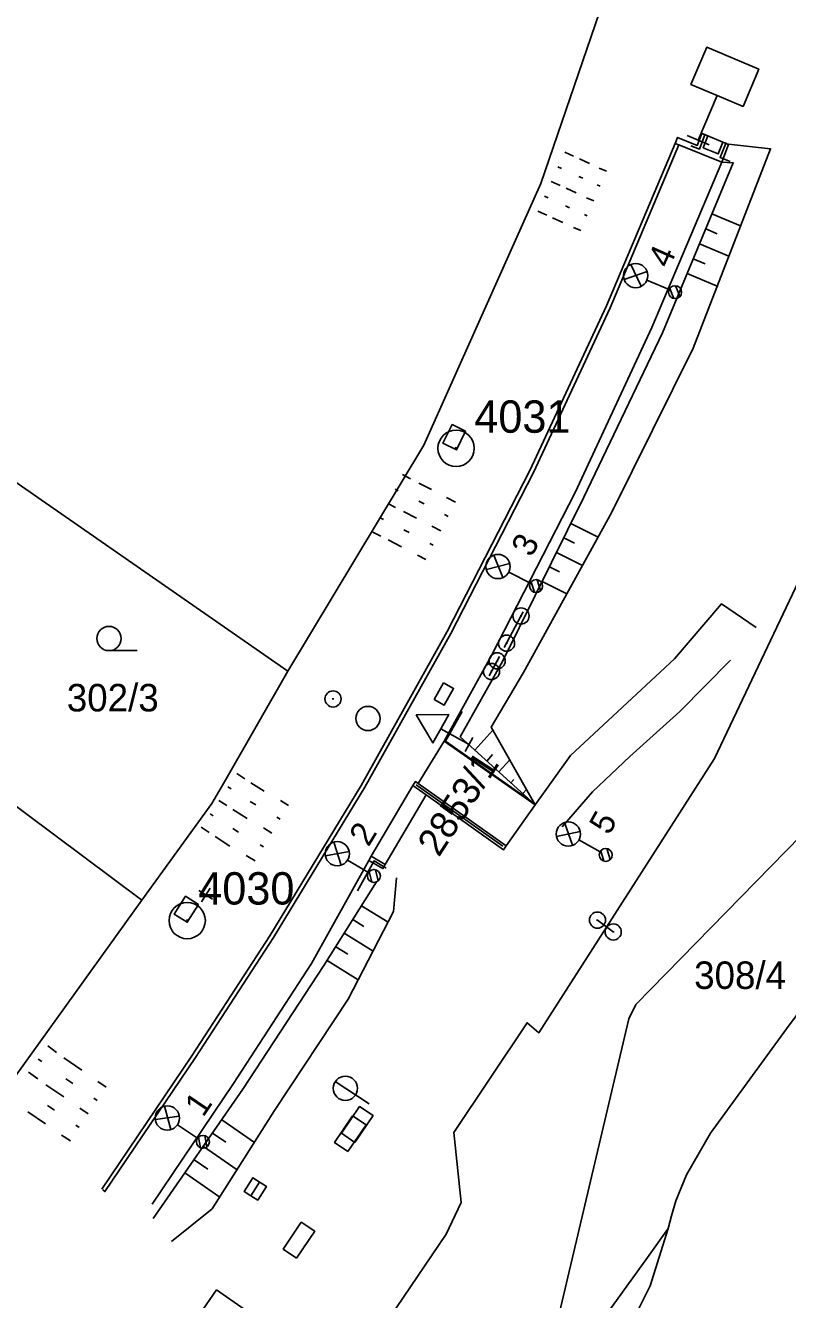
# Model space of a CAD drawing. Extents: x -558358 to -557517, y -1073786 to -1073189.
# Drawn here: x -558098.4 to -558051.3, y -1073345.8 to -1073267 of the extents above; entities that cross this region are included whole.
import ezdxf

# ---------------------------------------------------------------- set-up
doc = ezdxf.new("R2010")
doc.units = 0
for name, color, linetype in [('Body', 7, 'Continuous'), ('bubliny', 7, 'Continuous'), ('Hranice parcel', 7, 'Continuous'), ('Kanalizace nadzemní', 7, 'Continuous'), ('Lomové body_cisla', 7, 'Continuous'), ('Lomové body_krizky', 7, 'Continuous'), ('Nástupiště', 7, 'Continuous'), ('Návěst místo trati', 7, 'Continuous'), ('Parcelní čísla', 7, 'Continuous'), ('Plot - zábradlí', 7, 'Continuous'), ('Přejezd - štěrkové lože', 7, 'Continuous'), ('Sonda - šrafa - vrstevnice', 7, 'Continuous'), ('Svazek obcí údolí Desné', 7, 'Continuous'), ('Vedení nerozlišené', 7, 'Continuous'), ('Vedení neurčené', 7, 'Continuous'), ('Vrstva 60', 7, 'Continuous'), ('Značky kultur', 7, 'Continuous'), ('Zpevněná plocha - svah', 7, 'Continuous')]:
    doc.layers.add(name, color=color, linetype=linetype)

msp = doc.modelspace()

# ---------------------------------------------------------------- linework, layer by layer
at = {"layer": 'Body'}
for p, q in [((-558072.015, -1073291.684), (-558071.176, -1073292.092)), ((-558071.741, -1073293.25), (-558072.586, -1073292.839)), ((-558088.512, -1073320.845), (-558087.712, -1073321.364)), ((-558088.401, -1073322.455), (-558089.212, -1073321.963))]:
    msp.add_line(p, q, dxfattribs=at)
for points in [[(-558071.176, -1073292.092), (-558071.741, -1073293.25), (-558072.586, -1073292.839), (-558072.015, -1073291.684), (-558071.176, -1073292.092)], [(-558072.586, -1073292.839), (-558072.586, -1073292.839), (-558072.015, -1073291.684), (-558072.015, -1073291.684)], [(-558071.741, -1073293.25), (-558071.741, -1073293.25), (-558071.176, -1073292.092), (-558071.176, -1073292.092)], [(-558087.712, -1073321.364), (-558088.401, -1073322.455), (-558089.212, -1073321.963), (-558088.512, -1073320.845), (-558087.712, -1073321.364)], [(-558089.212, -1073321.963), (-558089.212, -1073321.963), (-558088.512, -1073320.845), (-558088.512, -1073320.845)]]:
    msp.add_lwpolyline(points, dxfattribs=at)
at = {"layer": 'bubliny'}
for p, q in [((-558067.612, -1073303.25), (-558068.784, -1073305.464)), ((-558067.802, -1073303.515), (-558067.702, -1073303.515)), ((-558068.694, -1073305.199), (-558068.594, -1073305.199)), ((-558069.081, -1073306.029), (-558069.722, -1073307.216)), ((-558069.273, -1073306.292), (-558069.173, -1073306.292)), ((-558069.63, -1073306.953), (-558069.53, -1073306.953)), ((-558071.21, -1073311.905), (-558070.722, -1073311.033)), ((-558063.07, -1073322.324), (-558062.97, -1073322.324)), ((-558063.02, -1073322.324), (-558062.044, -1073323.057)), ((-558062.094, -1073323.057), (-558061.994, -1073323.057))]:
    msp.add_line(p, q, dxfattribs=at)
msp.add_lwpolyline([(-558070.966, -1073311.469), (-558072.711, -1073310.492), (-558072.222, -1073309.619), (-558074.238, -1073309.636), (-558073.2, -1073311.364), (-558072.711, -1073310.492)], dxfattribs=at)
for centre in [(-558067.752, -1073303.515), (-558068.644, -1073305.199), (-558069.223, -1073306.292), (-558069.58, -1073306.953), (-558063.02, -1073322.324), (-558062.044, -1073323.057)]:
    msp.add_circle(centre, 0.5, dxfattribs=at)
at = {"layer": 'Hranice parcel'}
for p, q in [((-558099.14, -1073295.15), (-558082.18, -1073306.93)), ((-558101.25, -1073313.61), (-558091.21, -1073321.1)), ((-558058.43, -1073340.61), (-558058.64, -1073341.4)), ((-558058.64, -1073341.4), (-558059.76, -1073344.95))]:
    msp.add_line(p, q, dxfattribs=at)
for points in [[(-558045.59, -1073322.77), (-558047.44, -1073324.48), (-558048.82, -1073325.91), (-558050.13, -1073327.44), (-558051.32, -1073329.04), (-558056.02, -1073335.51), (-558057.5, -1073338.08), (-558058.16, -1073339.69), (-558058.43, -1073340.61)], [(-558083.8, -1073372.96), (-558071.77, -1073359.59), (-558059.92, -1073343.2), (-558058.64, -1073341.4)], [(-558059.76, -1073344.95), (-558061.55, -1073348.53), (-558062.6, -1073350.23), (-558070.37, -1073360.66), (-558089.91, -1073385.65), (-558114.04, -1073415.6), (-558119.93, -1073422.75), (-558120.74, -1073423.38), (-558121.71, -1073423.79), (-558122.74, -1073423.86)]]:
    msp.add_lwpolyline(points, dxfattribs=at)
at = {"layer": 'Kanalizace nadzemní'}
msp.add_lwpolyline([(-558084.466, -1073339.369), (-558084.889, -1073339.1), (-558084.352, -1073338.255), (-558083.507, -1073338.792), (-558084.044, -1073339.637), (-558084.466, -1073339.369), (-558083.93, -1073338.523)], dxfattribs=at)
at = {"layer": 'Lomové body_cisla'}
for p, q in [((-558061.362, -1073282.699), (-558059.951, -1073282.215)), ((-558060.315, -1073283.124), (-558060.965, -1073281.782)), ((-558059.965, -1073282.752), (-558058.583, -1073283.334)), ((-558058.292, -1073283.879), (-558058.542, -1073283.265)), ((-558057.914, -1073283.748), (-558058.181, -1073283.093)), ((-558068.882, -1073301.143), (-558069.43, -1073299.756)), ((-558069.894, -1073300.64), (-558068.451, -1073300.264)), ((-558068.506, -1073300.798), (-558067.172, -1073301.483)), ((-558066.922, -1073302.048), (-558067.125, -1073301.417)), ((-558066.536, -1073301.945), (-558066.752, -1073301.272)), ((-558064.555, -1073317.698), (-558065.052, -1073316.291)), ((-558065.548, -1073317.158), (-558064.092, -1073316.835)), ((-558078.879, -1073318.925), (-558079.325, -1073317.502)), ((-558064.166, -1073317.366), (-558062.858, -1073318.099)), ((-558062.239, -1073318.585), (-558062.431, -1073317.904)), ((-558079.852, -1073318.351), (-558078.385, -1073318.079)), ((-558078.479, -1073318.608), (-558077.197, -1073319.387)), ((-558062.629, -1073318.673), (-558062.809, -1073318.035)), ((-558076.989, -1073319.969), (-558077.146, -1073319.324)), ((-558076.596, -1073319.894), (-558076.763, -1073319.207)), ((-558090.373, -1073334.661), (-558088.896, -1073334.455)), ((-558089.426, -1073335.278), (-558089.81, -1073333.836)), ((-558089.012, -1073334.978), (-558087.766, -1073335.813)), ((-558087.584, -1073336.404), (-558087.713, -1073335.753)), ((-558087.188, -1073336.346), (-558087.325, -1073335.653))]:
    msp.add_line(p, q, dxfattribs=at)
for points in [[(-558078.46, -1073336.644), (-558079.29, -1073336.085), (-558078.172, -1073334.426), (-558077.342, -1073334.985), (-558078.46, -1073336.644)], [(-558078.024, -1073336.07), (-558078.854, -1073335.511), (-558077.736, -1073333.852), (-558076.906, -1073334.411), (-558078.024, -1073336.07)], [(-558081.637, -1073343.226), (-558082.467, -1073342.667), (-558081.349, -1073341.008), (-558080.519, -1073341.567), (-558081.637, -1073343.226)]]:
    msp.add_lwpolyline(points, dxfattribs=at)
for centre, radius in [((-558060.656, -1073282.464), 0.749), ((-558058.215, -1073283.49), 0.4), ((-558058.215, -1073283.49), 0.4), ((-558069.173, -1073300.458), 0.749), ((-558066.816, -1073301.665), 0.4), ((-558066.816, -1073301.665), 0.4), ((-558064.821, -1073317.003), 0.749), ((-558079.12, -1073318.221), 0.749), ((-558062.509, -1073318.295), 0.4), ((-558062.509, -1073318.295), 0.4), ((-558076.855, -1073319.595), 0.4), ((-558076.855, -1073319.595), 0.4), ((-558089.636, -1073334.564), 0.749), ((-558087.434, -1073336.036), 0.4), ((-558087.434, -1073336.036), 0.4)]:
    msp.add_circle(centre, radius, dxfattribs=at)
at = {"layer": 'Lomové body_krizky'}
for points in [[(-558054.902, -1073274.332), (-558052.311, -1073274.624), (-558057.102, -1073286.961), (-558062.128, -1073297.092), (-558067.594, -1073307.007), (-558069.593, -1073310.386), (-558066.875, -1073315.201)], [(-558066.875, -1073315.201), (-558071.513, -1073311), (-558068.878, -1073306.282), (-558063.859, -1073296.178), (-558059.005, -1073286.004), (-558054.622, -1073275.498), (-558055.333, -1073275.445)], [(-558090.522, -1073340.781), (-558084.963, -1073332.785), (-558079.942, -1073325.14), (-558076.703, -1073319.95)], [(-558075.447, -1073319.704), (-558075.635, -1073321.794), (-558078.439, -1073327.212), (-558083.002, -1073334.109), (-558086.852, -1073340.18), (-558089.38, -1073342.195)]]:
    msp.add_lwpolyline(points, dxfattribs=at)
at = {"layer": 'Nástupiště'}
msp.add_line((-558056.197, -1073273.829), (-558055.267, -1073274.207), dxfattribs=at)
msp.add_lwpolyline([(-558057.98, -1073274.385), (-558058.205, -1073274.3), (-558058.06, -1073273.92), (-558056.841, -1073274.41), (-558056.554, -1073273.686), (-558056.197, -1073273.829), (-558056.476, -1073274.557), (-558055.55, -1073274.938), (-558055.267, -1073274.207), (-558054.903, -1073274.356), (-558055.333, -1073275.445)], close=True, dxfattribs=at)
for points in [[(-558058.205, -1073274.3), (-558062.453, -1073284.346), (-558067.2, -1073294.524), (-558072.31, -1073304.481), (-558077.642, -1073314), (-558083.287, -1073323.291), (-558088.119, -1073330.713), (-558093.699, -1073338.955)], [(-558057.98, -1073274.385), (-558062.235, -1073284.458), (-558066.982, -1073294.636), (-558072.092, -1073304.593), (-558077.424, -1073314.112), (-558083.069, -1073323.403), (-558087.901, -1073330.825), (-558093.497, -1073339.112), (-558093.633, -1073339)], [(-558055.333, -1073275.445), (-558059.656, -1073285.684), (-558064.408, -1073295.879), (-558069.583, -1073305.951), (-558072.499, -1073311.254), (-558074.109, -1073313.879)], [(-558074.438, -1073314.006), (-558077.015, -1073318.379), (-558076.161, -1073318.88)], [(-558074.109, -1073313.879), (-558074.282, -1073313.753), (-558074.438, -1073314.006), (-558073.627, -1073314.572)], [(-558090.573, -1073339.885), (-558085.54, -1073332.431), (-558080.709, -1073325.01), (-558077.164, -1073318.639)], [(-558076.161, -1073318.88), (-558076.297, -1073319.14), (-558077.164, -1073318.639), (-558077.015, -1073318.379)]]:
    msp.add_lwpolyline(points, dxfattribs=at)
at = {"layer": 'Návěst místo trati'}
for p, q in [((-558057.479, -1073273.799), (-558056.098, -1073274.383)), ((-558079.431, -1073308.647), (-558079.331, -1073308.647)), ((-558079.431, -1073308.647), (-558079.331, -1073308.647)), ((-558086.836, -1073321.032), (-558087.68, -1073320.496)), ((-558086.99, -1073320.342), (-558087.526, -1073321.186))]:
    msp.add_line(p, q, dxfattribs=at)
msp.add_lwpolyline([(-558056.789, -1073274.091), (-558055.622, -1073271.327), (-558054.009, -1073272.008), (-558053.037, -1073269.705), (-558056.261, -1073268.343), (-558057.234, -1073270.646), (-558055.622, -1073271.327)], dxfattribs=at)
for centre, radius in [((-558079.381, -1073308.647), 0.5), ((-558079.381, -1073308.647), 0.5), ((-558077.223, -1073309.856), 0.75)]:
    msp.add_circle(centre, radius, dxfattribs=at)
at = {"layer": 'Plot - zábradlí'}
msp.add_line((-558074.241, -1073313.962), (-558068.875, -1073317.761), dxfattribs=at)
for points in [[(-558057.234, -1073274.441), (-558056.714, -1073274.642), (-558056.347, -1073273.699)], [(-558055.05, -1073274.228), (-558055.429, -1073275.168), (-558054.805, -1073275.415)], [(-558066.954, -1073315.094), (-558072.425, -1073311.253), (-558071.392, -1073309.433)], [(-558077.861, -1073320.516), (-558076.84, -1073318.669), (-558076.089, -1073319.12)]]:
    msp.add_lwpolyline(points, dxfattribs=at)
at = {"layer": 'Přejezd - štěrkové lože'}
for p, q in [((-558062.454, -1073276.015), (-558062.909, -1073275.817)), ((-558062.852, -1073276.931), (-558063.034, -1073276.853)), ((-558063.251, -1073277.849), (-558063.704, -1073277.652)), ((-558063.649, -1073278.766), (-558063.83, -1073278.687)), ((-558064.047, -1073279.683), (-558064.499, -1073279.487)), ((-558071.804, -1073296.471), (-558072.371, -1073296.179)), ((-558072.262, -1073297.36), (-558072.484, -1073297.246)), ((-558072.72, -1073298.249), (-558073.263, -1073297.97)), ((-558073.177, -1073299.139), (-558073.39, -1073299.029)), ((-558073.635, -1073300.028), (-558074.155, -1073299.76)), ((-558082.13, -1073315.231), (-558082.64, -1073314.923)), ((-558082.647, -1073316.087), (-558082.855, -1073315.961)), ((-558083.163, -1073316.943), (-558083.695, -1073316.622)), ((-558083.68, -1073317.799), (-558083.897, -1073317.668)), ((-558084.197, -1073318.655), (-558084.749, -1073318.322)), ((-558093.424, -1073332.648), (-558093.935, -1073332.308)), ((-558093.977, -1073333.481), (-558094.185, -1073333.343)), ((-558094.531, -1073334.314), (-558095.056, -1073333.965)), ((-558095.085, -1073335.147), (-558095.298, -1073335.005)), ((-558095.638, -1073335.979), (-558096.177, -1073335.621))]:
    msp.add_line(p, q, dxfattribs=at)
at = {"layer": 'Sonda - šrafa - vrstevnice'}
for p, q in [((-558065.049, -1073274.831), (-558064.512, -1073275.075)), ((-558063.505, -1073275.532), (-558064.139, -1073275.245)), ((-558065.462, -1073275.741), (-558065.246, -1073275.839)), ((-558065.876, -1073276.652), (-558065.332, -1073276.899)), ((-558063.917, -1073276.443), (-558064.171, -1073276.328)), ((-558066.29, -1073277.562), (-558066.071, -1073277.661)), ((-558064.33, -1073277.354), (-558064.966, -1073277.066)), ((-558066.703, -1073278.473), (-558066.153, -1073278.723)), ((-558064.742, -1073278.265), (-558064.997, -1073278.15)), ((-558065.154, -1073279.177), (-558065.793, -1073278.888)), ((-558055.938, -1073278.652), (-558054.163, -1073279.393)), ((-558056.323, -1073279.575), (-558055.604, -1073279.875)), ((-558056.708, -1073280.498), (-558054.887, -1073281.258)), ((-558057.093, -1073281.421), (-558056.356, -1073281.729)), ((-558057.478, -1073282.344), (-558055.611, -1073283.123)), ((-558075.089, -1073294.776), (-558074.595, -1073295.029)), ((-558075.544, -1073295.667), (-558075.348, -1073295.767)), ((-558073.286, -1073295.704), (-558074.074, -1073295.293)), ((-558076, -1073296.557), (-558075.513, -1073296.806)), ((-558073.749, -1073296.589), (-558074.068, -1073296.423)), ((-558076.456, -1073297.447), (-558076.262, -1073297.546)), ((-558074.211, -1073297.477), (-558075.02, -1073297.055)), ((-558074.674, -1073298.362), (-558075.001, -1073298.192)), ((-558064.663, -1073297.797), (-558062.978, -1073298.634)), ((-558076.912, -1073298.337), (-558076.431, -1073298.583)), ((-558075.136, -1073299.25), (-558075.966, -1073298.817)), ((-558065.108, -1073298.692), (-558064.449, -1073299.02)), ((-558065.553, -1073299.588), (-558063.944, -1073300.387)), ((-558065.998, -1073300.484), (-558065.37, -1073300.796)), ((-558066.443, -1073301.379), (-558064.911, -1073302.14)), ((-558070.608, -1073311.819), (-558069.484, -1073310.578)), ((-558069.867, -1073312.491), (-558069.507, -1073312.093)), ((-558069.126, -1073313.162), (-558068.448, -1073312.414)), ((-558085.34, -1073313.249), (-558084.838, -1073313.58)), ((-558083.634, -1073314.358), (-558084.477, -1073313.826)), ((-558068.385, -1073313.834), (-558068.203, -1073313.633)), ((-558085.891, -1073314.084), (-558085.692, -1073314.215)), ((-558067.643, -1073314.505), (-558067.412, -1073314.25)), ((-558086.442, -1073314.918), (-558085.947, -1073315.244)), ((-558084.7, -1073316.05), (-558085.582, -1073315.494)), ((-558084.167, -1073315.204), (-558084.512, -1073314.986)), ((-558086.993, -1073315.752), (-558086.796, -1073315.882)), ((-558087.543, -1073316.587), (-558087.056, -1073316.909)), ((-558085.766, -1073317.742), (-558086.686, -1073317.162)), ((-558085.233, -1073316.896), (-558085.593, -1073316.669)), ((-558077.628, -1073321.432), (-558075.98, -1073322.461)), ((-558078.158, -1073322.281), (-558077.471, -1073322.71)), ((-558078.687, -1073323.129), (-558076.903, -1073324.243)), ((-558079.217, -1073323.978), (-558078.475, -1073324.44)), ((-558079.746, -1073324.826), (-558077.825, -1073326.025)), ((-558097.04, -1073330.107), (-558096.498, -1073330.503)), ((-558097.629, -1073330.916), (-558097.406, -1073331.078)), ((-558094.921, -1073331.608), (-558096.038, -1073330.847)), ((-558098.219, -1073331.723), (-558097.644, -1073332.143)), ((-558095.484, -1073332.435), (-558095.927, -1073332.133)), ((-558096.047, -1073333.261), (-558097.148, -1073332.511)), ((-558097.173, -1073334.914), (-558098.259, -1073334.175)), ((-558096.61, -1073334.088), (-558097.047, -1073333.79)), ((-558086.269, -1073334.674), (-558084.247, -1073336.072)), ((-558086.838, -1073335.497), (-558086.016, -1073336.065)), ((-558087.407, -1073336.319), (-558085.319, -1073337.763)), ((-558087.976, -1073337.141), (-558087.127, -1073337.728)), ((-558088.544, -1073337.964), (-558086.391, -1073339.453))]:
    msp.add_line(p, q, dxfattribs=at)
at = {"layer": 'Svazek obcí údolí Desné'}
for p, q in [((-558086.59, -1073345.2), (-558088.33, -1073347.7)), ((-558078.52, -1073350.81), (-558086.59, -1073345.2))]:
    msp.add_line(p, q, dxfattribs=at)
for points in [[(-558082.18, -1073306.93), (-558073.77, -1073292.96), (-558066.53, -1073276.76), (-558060.05, -1073257.85), (-558056.4, -1073244.89), (-558045.6, -1073201.5), (-558043.139, -1073189.962)], [(-558025.68, -1073189.916), (-558032.09, -1073212.63), (-558035.15, -1073249.33), (-558039.97, -1073265.01), (-558041.24, -1073272.26), (-558045.55, -1073290.79), (-558055.77, -1073312.33), (-558066.64, -1073329.29), (-558067.37, -1073328.67), (-558071.91, -1073335.47), (-558071.45, -1073339.78), (-558072.38, -1073341.74), (-558078.52, -1073350.81)], [(-558066.74, -1073350.64), (-558065.9, -1073348.86), (-558061.08, -1073328.44), (-558060.65, -1073327.54), (-558046.7, -1073313.29), (-558030.4, -1073296.27), (-558015.33, -1073274.48), (-558010.02, -1073266.4), (-558006.82, -1073259.79), (-558003.58, -1073251.39), (-558001.93, -1073245.63), (-558000.3, -1073233.47), (-558000.14, -1073230.76), (-558000.21, -1073228.76), (-558000.67, -1073225.31), (-558001.93, -1073222.03), (-558003.18, -1073219.55), (-558003.41, -1073218.32), (-558003.28, -1073217.31), (-558002.8, -1073216.38), (-558000.9, -1073214.81), (-557999.34, -1073213.91), (-558005.3, -1073194.99), (-558007.236, -1073189.964)], [(-558082.18, -1073306.93), (-558086.02, -1073313.63), (-558086.89, -1073315.11), (-558091.21, -1073321.1)], [(-558091.21, -1073321.1), (-558099.53, -1073332.65), (-558131.71, -1073378.11), (-558132.32, -1073380.12), (-558138.4, -1073389.94), (-558139.67, -1073391.56)]]:
    msp.add_lwpolyline(points, dxfattribs=at)
at = {"layer": 'Vedení nerozlišené'}
msp.add_line((-558079.245, -1073332.315), (-558077.155, -1073333.686), dxfattribs=at)
msp.add_lwpolyline([(-558072.545, -1073307.649), (-558071.925, -1073307.995), (-558072.497, -1073309.024), (-558073.121, -1073308.678)], close=True, dxfattribs=at)
msp.add_circle((-558078.618, -1073332.726), 0.75, dxfattribs=at)
at = {"layer": 'Vrstva 60'}
for p, q in [((-558071.766, -1073293.148), (-558071.766, -1073293.148)), ((-558071.766, -1073293.148), (-558071.766, -1073293.148)), ((-558088.408, -1073322.352), (-558088.408, -1073322.352)), ((-558088.408, -1073322.352), (-558088.408, -1073322.352))]:
    msp.add_line(p, q, dxfattribs=at)
for centre, radius in [((-558071.766, -1073293.148), 1.125), ((-558071.766, -1073293.148), 0.045), ((-558088.408, -1073322.352), 1.125), ((-558088.408, -1073322.352), 0.045)]:
    msp.add_circle(centre, radius, dxfattribs=at)
at = {"layer": 'Značky kultur'}
msp.add_line((-558093.243, -1073305.66), (-558091.493, -1073305.66), dxfattribs=at)
msp.add_circle((-558093.243, -1073304.91), 0.75, dxfattribs=at)
at = {"layer": 'Zpevněná plocha - svah'}
msp.add_line((-558066.875, -1073315.201), (-558064.678, -1073312.141), dxfattribs=at)
for points in [[(-558064.678, -1073312.141), (-558062.076, -1073309.712), (-558058.247, -1073306.172), (-558055.343, -1073302.763), (-558053.202, -1073304.219)], [(-558054.794, -1073306.255), (-558057.916, -1073309.42), (-558061.014, -1073312.202), (-558063.334, -1073314.402), (-558065.21, -1073316.553)], [(-558072.499, -1073311.254), (-558066.875, -1073315.201), (-558068.665, -1073317.735)], [(-558074.109, -1073313.879), (-558068.665, -1073317.735), (-558068.829, -1073317.97), (-558073.627, -1073314.572), (-558076.161, -1073318.88)]]:
    msp.add_lwpolyline(points, dxfattribs=at)

# ---------------------------------------------------------------- texts
at = {"layer": 'Parcelní čísla'}
for s, p in [('302/3', (-558095.858, -1073309.42)), ('308/4', (-558057.037, -1073326.581))]:
    msp.add_text(s, height=1.7, dxfattribs=at).set_placement(p)
msp.add_text('2853/1', height=1.7, rotation=57, dxfattribs=at).set_placement((-558072.837, -1073318.483))
at = {"layer": 'Vedení neurčené'}
for s, rotation, p in [('4', 66.02437, (-558058.584, -1073282.073)), ('3', 62.8328, (-558067.089, -1073299.936)), ('5', 60.74494, (-558062.302, -1073317.127)), ('2', 58.71809, (-558077.188, -1073317.844)), ('1', 55.88491, (-558087.419, -1073334.562))]:
    msp.add_text(s, height=1.5, rotation=rotation, dxfattribs=at).set_placement(p)
at = {"layer": 'Vrstva 60'}
for s, p in [('4031', (-558070.639, -1073292.184)), ('4030', (-558087.722, -1073321.362))]:
    msp.add_text(s, height=2, dxfattribs=at).set_placement(p)

doc.saveas('drawing.dxf')
